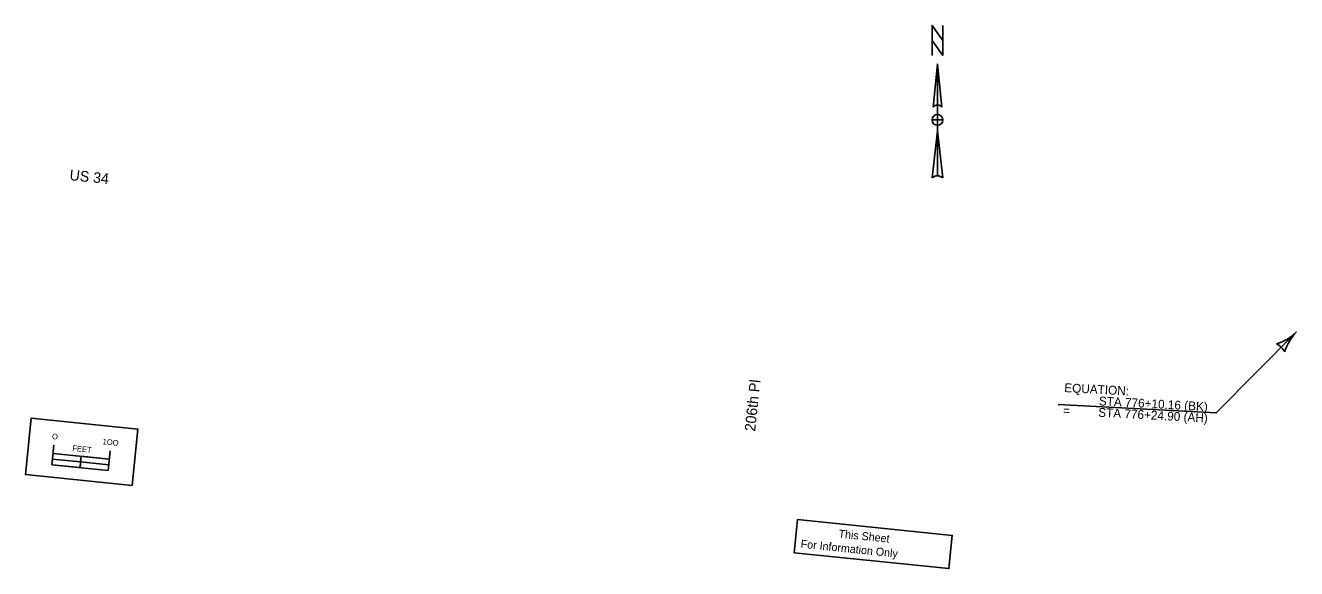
# Model space of a CAD drawing. Extents: x 22712865 to 22760106, y 6235088 to 6238602.
# Drawn here: x 22752425 to 22754677, y 6237044 to 6238006 of the extents above; entities that cross this region are included whole.
import ezdxf

# ---------------------------------------------------------------- set-up
doc = ezdxf.new("R2010")
doc.units = 0
for name, color, linetype in [('_CIVIL_CONSTRUCTION', 7, 'Continuous'), ('Contours Major', 7, 'Continuous'), ('Default', 7, 'Continuous'), ('Entrance', 7, 'Continuous')]:
    doc.layers.add(name, color=color, linetype=linetype)

msp = doc.modelspace()

# ---------------------------------------------------------------- linework, layer by layer
at = {"layer": '_CIVIL_CONSTRUCTION'}
msp.add_line((22752522, 6237223), (22752524, 6237242.9), dxfattribs=at)
msp.add_line((22752522, 6237223), (22752524, 6237242.9), dxfattribs=at)
for points in [[(22752435.4, 6237310.3), (22752624.5, 6237291), (22752614.3, 6237191.5), (22752425.3, 6237210.8)], [(22752425.3, 6237210.8), (22752435.4, 6237310.3), (22752624.5, 6237291), (22752614.3, 6237191.5)], [(22752472.3, 6237228.1), (22752522, 6237223), (22752523, 6237233.1), (22752473.3, 6237238.1)], [(22752523, 6237233.1), (22752572.8, 6237228), (22752573.8, 6237237.9), (22752524, 6237242.9)]]:
    msp.add_lwpolyline(points, close=True, dxfattribs=at)
for points in [[(22752475.8, 6237262.9), (22752472.3, 6237228.1), (22752571.8, 6237218), (22752575.3, 6237252.8)], [(22752474.3, 6237248), (22752573.8, 6237237.9)]]:
    msp.add_lwpolyline(points, dxfattribs=at)
at = {"layer": 'Contours Major'}
msp.add_lwpolyline([(22754677, 6237463.3), (22754534.8, 6237319.8), (22754254.8, 6237334.8)], dxfattribs=at)
for centre, radius, start, end in [((22754616.6, 6237523.1), 85, 287.1843, 315.2568), ((22754737.4, 6237403.5), 85, 135.2568, 163.3292), ((22754626.8, 6237412.7), 32.8, 27.5234, 62.9901)]:
    msp.add_arc(centre, radius, start, end, dxfattribs=at)
at = {"layer": 'Entrance'}
for p, q in [((22754040.8, 6237937.1), (22754048.4, 6237861.1)), ((22754040.8, 6237937.1), (22754040.8, 6237739.4)), ((22754033.1, 6237861.1), (22754033.1, 6237861.1)), ((22754033.4, 6237861.8), (22754034.9, 6237863.4)), ((22754040.8, 6237828.8), (22754040.8, 6237828.7)), ((22754031.2, 6237735.6), (22754040.8, 6237819.2))]:
    msp.add_line(p, q, dxfattribs=at)
for points in [[(22754050.3, 6237952.3), (22754031.2, 6237979), (22754031.2, 6238005.6), (22754050.3, 6237979)], [(22753786.9, 6237072.2), (22754061.1, 6237044.2), (22754067.1, 6237103), (22753792.9, 6237131)], [(22753792.9, 6237131), (22754067.1, 6237103), (22754061.1, 6237044.2), (22753786.9, 6237072.2)]]:
    msp.add_lwpolyline(points, close=True, dxfattribs=at)
for points in [[(22754031.2, 6237952.3), (22754031.2, 6238005.6), (22754050.3, 6237979), (22754050.3, 6238005.6)], [(22754033.1, 6237861.1), (22754040.8, 6237937.1), (22754040.8, 6237864.9)], [(22754050.3, 6237838.3), (22754040.8, 6237838.3), (22754040.8, 6237847.8)], [(22754040.8, 6237828.7), (22754040.8, 6237838.3), (22754031.2, 6237838.3)], [(22754040.8, 6237739.4), (22754040.8, 6237819.2), (22754050.3, 6237735.6)]]:
    msp.add_lwpolyline(points, dxfattribs=at)
for centre, radius, start, end in [((22754040.8, 6237838.3), 9.51, 90, 180), ((22754040.8, 6237855.4), 9.51, 90.0204, 143.1257), ((22754040.8, 6237855.4), 9.5, 36.8481, 90.0218), ((22754040.8, 6237838.3), 9.51, 0, 90), ((22754040.8, 6237838.3), 9.51, 180, 270), ((22754040.8, 6237838.3), 9.51, 270, 360), ((22754040.7, 6237725.6), 13.8, 89.9894, 133.619), ((22754040.8, 6237725.6), 13.8, 46.4021, 90.0006)]:
    msp.add_arc(centre, radius, start, end, dxfattribs=at)

# ---------------------------------------------------------------- texts
at = {"layer": '_CIVIL_CONSTRUCTION'}
for s, p in [('O', (22752471.9, 6237273.4)), ('O', (22752471.9, 6237273.4)), ('FEET', (22752508, 6237252.6)), ('1OO', (22752561.6, 6237264.2)), ('1OO', (22752561.6, 6237264.2))]:
    msp.add_text(s, height=10, rotation=354.1676, dxfattribs=at).set_placement(p)
at = {"layer": 'Contours Major'}
for s, height, p in [('EQUATION:', 15.6, (22754265.2, 6237356.7)), ('=', 15.6, (22754263, 6237316.4)), ('STA 776+24.90 (AH)', 15.601, (22754325.3, 6237313.1)), ('STA 776+10.16 (BK)', 15.601, (22754326.4, 6237333.2))]:
    msp.add_text(s, height=height, rotation=356.9456, dxfattribs=at).set_placement(p)
at = {"layer": 'Default'}
for s, rotation, p in [('US 34', 354.171, (22752502.8, 6237731.9)), ('206th Pl', 84.171, (22753717.9, 6237286.3))]:
    msp.add_text(s, height=18.75, rotation=rotation, dxfattribs=at).set_placement(p)
at = {"layer": 'Entrance'}
for s, height, p in [('This Sheet', 14.17, (22753865.1, 6237099.2)), ('For Information Only', 14.175, (22753798, 6237081.2))]:
    msp.add_text(s, height=height, rotation=354.1676, dxfattribs=at).set_placement(p)

doc.saveas('drawing.dxf')
